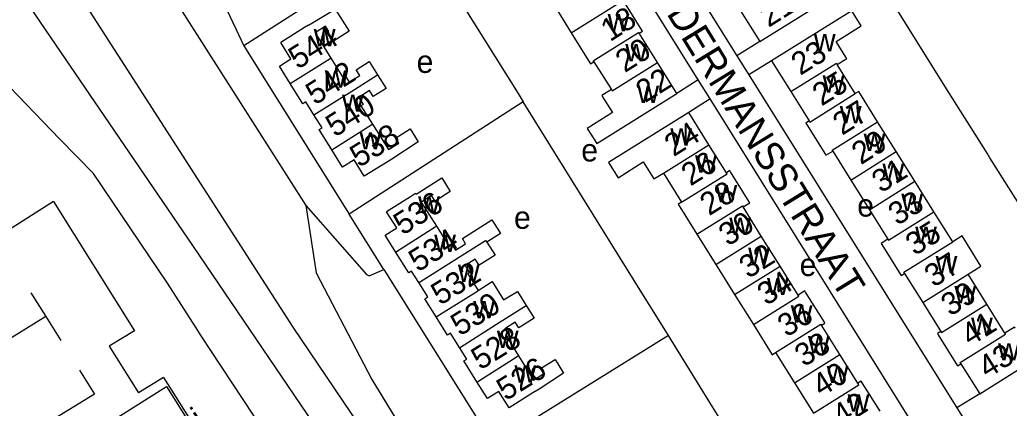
# Model space of a CAD drawing. Extents: x 159294 to 161936, y 384538 to 386517.
# Drawn here: x 159670 to 159845.8, y 385777.9 to 385846.8 of the extents above; entities that cross this region are included whole.
import ezdxf

# ---------------------------------------------------------------- set-up
doc = ezdxf.new("R2010")
doc.units = 0
for name, color, linetype in [('BLT_Basislijn', 7, 'Continuous'), ('BLT_Bebouwing', 7, 'Continuous'), ('BLT_Centroide', 7, 'Continuous'), ('BLT_Huisnummer', 7, 'Continuous'), ('BLT_Huisnummer_ tussenligend', 7, 'Continuous'), ('BLT_Huisnummer_zonder_bebouwing', 7, 'Continuous'), ('BLT_Onderverdeling_panden', 7, 'Continuous'), ('BLT_Plantopo', 7, 'Continuous'), ('BLT_Straatnaam', 7, 'Continuous'), ('BLT_Vlakafsluiter', 7, 'Continuous')]:
    doc.layers.add(name, color=color, linetype=linetype)

msp = doc.modelspace()

# ---------------------------------------------------------------- linework, layer by layer
at = {"layer": 'BLT_Basislijn'}
for p, q in [((159790.53, 385836.17), (159753.6, 385895.33)), ((159740.67, 385861.99), (159709.78, 385842.22)), ((159834.31, 385835.04), (159817.97, 385861.31)), ((159706.45, 385849.41), (159709.78, 385842.22)), ((159801.45, 385842.96), (159797.39, 385840.47)), ((159709.78, 385842.22), (159728.49, 385812.31)), ((159803.56, 385839.56), (159799.51, 385837.07)), ((159790.53, 385836.17), (159786.73, 385833.76)), ((159792.65, 385832.78), (159790.53, 385836.17)), ((159758.52, 385833.74), (159759.43, 385832.28)), ((159841.82, 385823.15), (159834.31, 385835.04)), ((159759.43, 385832.28), (159728.49, 385812.31)), ((159779.17, 385800.53), (159759.43, 385832.28)), ((159792.65, 385832.78), (159788.85, 385830.37)), ((159829.58, 385773.62), (159792.65, 385832.78)), ((159676.02, 385814.58), (159637.93, 385790.31)), ((159676.02, 385814.58), (159690.39, 385791.62)), ((159734.67, 385802.49), (159728.49, 385812.31)), ((159734.67, 385802.49), (159754.35, 385771.09)), ((159785.25, 385790.76), (159779.17, 385800.53)), ((159674.66, 385794.14), (159649.77, 385778.85)), ((159690.39, 385791.62), (159685.89, 385788.86)), ((159702.24, 385790.69), (159701.2, 385792.32)), ((159703.93, 385788.12), (159702.24, 385790.69)), ((159793.08, 385778.13), (159785.25, 385790.76)), ((159685.89, 385788.86), (159691.08, 385780.58)), ((159680.63, 385784.6), (159683.28, 385780.36)), ((159695.57, 385783.34), (159691.08, 385780.58)), ((159695.57, 385783.34), (159772.56, 385660.32)), ((159840.51, 385780.44), (159836.47, 385777.93)), ((159803.66, 385760.87), (159793.08, 385778.13))]:
    msp.add_line(p, q, dxfattribs=at)
for points in [[(159760.43, 385899.6), (159797.39, 385840.47)], [(159681.58, 385875.5), (159720.83, 385813.84)], [(159672.14, 385864.36), (159718.49, 385792.26), (159734.77, 385768.17), (159772.32, 385708.21), (159809.55, 385648.76), (159856.03, 385574.41), (159873.73, 385548.57), (159892.72, 385518.61)], [(159743.98, 385856.93), (159744.67, 385855.88), (159758.52, 385833.74)], [(159879.9, 385516.8), (159880.33, 385519.48), (159867.2, 385540.44), (159859.25, 385553.53), (159846.62, 385579.07), (159838.32, 385592.49), (159800.14, 385653.57), (159788.51, 385666.46), (159777.48, 385684.4), (159767.2, 385706.17), (159746.01, 385740.12), (159700.77, 385806.77), (159672.01, 385848.87)], [(159611.36, 385798.1), (159616.53, 385804.68), (159648.78, 385842.99), (159651.58, 385845.19), (159656.35, 385845.62), (159659.23, 385844.2), (159677.11, 385825.62)], [(159797.39, 385840.47), (159799.51, 385837.07)], [(159799.51, 385837.07), (159836.47, 385777.93)], [(159701.2, 385792.32), (159696.28, 385800.04), (159683.08, 385819.53), (159677.11, 385825.62)], [(159848.33, 385812.79), (159842.33, 385822.34), (159841.82, 385823.15)], [(159720.83, 385813.84), (159731.58, 385801.6), (159732.05, 385801.39), (159734.67, 385802.49)], [(159722.65, 385801.89), (159732.54, 385782.95), (159752.05, 385751.03), (159780.98, 385704.72), (159792.12, 385692.39), (159803.4, 385674.29), (159814.16, 385651.74), (159831.62, 385623.7)], [(159672, 385798.37), (159674.66, 385794.14)], [(159674.66, 385794.14), (159677.31, 385789.9)], [(159785.25, 385790.76), (159757.72, 385773.66), (159754.35, 385771.09)], [(159781.81, 385666), (159780.88, 385667.5), (159761.1, 385700), (159741.96, 385730.52), (159703.93, 385788.12)], [(159683.28, 385780.36), (159667.08, 385770.41), (159667.87, 385769.15)], [(159836.47, 385777.93), (159848.4, 385758.85)]]:
    msp.add_lwpolyline(points, dxfattribs=at)
at = {"layer": 'BLT_Bebouwing'}
for p, q in [((159720.6, 385845.47), (159716.36, 385842.82)), ((159721.3, 385845.9), (159720.6, 385845.47)), ((159735.45, 385821.7), (159731.21, 385819.05)), ((159736.1, 385822.1), (159735.45, 385821.7)), ((159739.42, 385815.41), (159735.17, 385812.76)), ((159762.24, 385781.27), (159761.17, 385780.6)), ((159761.17, 385780.6), (159756.93, 385777.95))]:
    msp.add_line(p, q, dxfattribs=at)
for points in [[(159801.45, 385842.96), (159815.69, 385851.85), (159813.99, 385854.54), (159809.52, 385851.73), (159807.76, 385854.53)], [(159764.61, 385849.89), (159767.96, 385844.52)], [(159780.53, 385844.99), (159777.21, 385850.3)], [(159721.3, 385845.9), (159726.03, 385848.73), (159728.5, 385844.8), (159725.71, 385843.05), (159724.71, 385844.64), (159724.92, 385844.77), (159724.34, 385845.7), (159722.46, 385844.52), (159725.27, 385840.05)], [(159798.02, 385848.45), (159801.45, 385842.96)], [(159816.74, 385840.18), (159815, 385842.96), (159819.47, 385845.77), (159817.78, 385848.46), (159803.56, 385839.56)], [(159767.96, 385844.52), (159771.29, 385839.21)], [(159780.04, 385844.44), (159780.63, 385844.81), (159780.53, 385844.99)], [(159783.28, 385839.28), (159780.04, 385844.44)], [(159718.06, 385835.53), (159716.12, 385838.63), (159718.18, 385839.92), (159716.36, 385842.82)], [(159725.27, 385840.05), (159727.35, 385836.74), (159727.75, 385836.99), (159728.52, 385835.76), (159730.42, 385836.95), (159729.78, 385837.97), (159732.1, 385839.42), (159733.57, 385837.07)], [(159771.29, 385839.21), (159771.4, 385839.03), (159771.99, 385839.4)], [(159771.99, 385839.4), (159775.1, 385834.44)], [(159786.73, 385833.76), (159783.28, 385839.28)], [(159803.56, 385839.56), (159806.99, 385834.08)], [(159815.19, 385838.88), (159816.89, 385839.95), (159816.74, 385840.18)], [(159818.42, 385833.73), (159815.19, 385838.88)], [(159722.25, 385829.97), (159720.82, 385832.25), (159720.31, 385831.93), (159718.06, 385835.53)], [(159733.57, 385837.07), (159735.09, 385834.65), (159732.79, 385833.21), (159732.13, 385834.26), (159730.22, 385833.06), (159731.02, 385831.79), (159730.62, 385831.54), (159732.65, 385828.3)], [(159773.53, 385833.18), (159775.29, 385830.36), (159770.81, 385827.55), (159772.49, 385824.86), (159786.73, 385833.76)], [(159775.1, 385834.44), (159773.4, 385833.37), (159773.53, 385833.18)], [(159806.99, 385834.08), (159810.25, 385828.88)], [(159822.38, 385828.73), (159819.02, 385834.11), (159818.42, 385833.73)], [(159788.85, 385830.37), (159774.59, 385821.48), (159776.28, 385818.78), (159780.76, 385821.59), (159782.64, 385818.57)], [(159792.42, 385824.64), (159788.85, 385830.37)], [(159725.42, 385823.77), (159723.19, 385827.34), (159723.7, 385827.65), (159722.25, 385829.97)], [(159810.25, 385828.88), (159809.65, 385828.51), (159809.77, 385828.32)], [(159825.7, 385823.43), (159822.38, 385828.73)], [(159732.65, 385828.3), (159735.49, 385823.78), (159737.32, 385824.93), (159736.75, 385825.84), (159739.34, 385827.47), (159740.8, 385825.14), (159736.1, 385822.1)], [(159809.77, 385828.32), (159813.13, 385822.94)], [(159731.21, 385819.05), (159729.4, 385821.95), (159727.36, 385820.67), (159725.42, 385823.77)], [(159795.52, 385819.68), (159792.42, 385824.64)], [(159813.13, 385822.94), (159813.21, 385822.8), (159814.4, 385823.54)], [(159814.4, 385823.54), (159817.63, 385818.38)], [(159828.99, 385818.17), (159825.7, 385823.43)], [(159782.64, 385818.57), (159782.65, 385818.57), (159784.34, 385819.63)], [(159784.34, 385819.63), (159787.57, 385814.48)], [(159796.23, 385819.85), (159796.11, 385820.05), (159795.52, 385819.68)], [(159799.56, 385814.53), (159796.23, 385819.85)], [(159740.4, 385815.88), (159744.95, 385818.76), (159746.48, 385816.34), (159743.77, 385814.63), (159743.14, 385815.62), (159741.32, 385814.47), (159744.02, 385810.21)], [(159817.63, 385818.38), (159820.92, 385813.12)], [(159832.39, 385812.75), (159828.99, 385818.17)], [(159740.4, 385815.88), (159740.33, 385815.99), (159739.42, 385815.41)], [(159787.57, 385814.48), (159786.98, 385814.1), (159790.3, 385808.78)], [(159798.49, 385813.6), (159799.67, 385814.35), (159799.56, 385814.53)], [(159736.77, 385805.64), (159734.93, 385808.59), (159736.98, 385809.87), (159735.17, 385812.76)], [(159801.72, 385808.44), (159798.49, 385813.6)], [(159820.92, 385813.12), (159824.19, 385807.87)], [(159835.72, 385807.42), (159832.39, 385812.75)], [(159744.02, 385810.21), (159746.22, 385806.72), (159746.72, 385807.03), (159747.42, 385805.93), (159749.21, 385807.06), (159748.62, 385808.01), (159753.87, 385811.33), (159755.21, 385809.21)], [(159755.21, 385809.21), (159755.42, 385808.88), (159752.97, 385807.33)], [(159752.97, 385807.33), (159754.43, 385805.03), (159751.6, 385803.24), (159750.91, 385804.34), (159749.1, 385803.2), (159749.91, 385801.91), (159749.58, 385801.7), (159751.41, 385798.76)], [(159790.3, 385808.78), (159793.65, 385803.4)], [(159805.06, 385803.09), (159801.72, 385808.44)], [(159824.19, 385807.87), (159823.01, 385807.13), (159823.12, 385806.95)], [(159838.47, 385801.69), (159840.73, 385803.11), (159837.38, 385808.46), (159835.72, 385807.43)], [(159740.89, 385800.18), (159739.62, 385802.21), (159739.12, 385801.89), (159736.77, 385805.64)], [(159823.12, 385806.95), (159826.45, 385801.63)], [(159793.65, 385803.4), (159796.99, 385798.05)], [(159808.27, 385797.94), (159805.06, 385803.09)], [(159751.41, 385798.76), (159753.92, 385800.34), (159755.95, 385797.09), (159758.39, 385798.6), (159759.95, 385796.08)], [(159826.45, 385801.63), (159826.57, 385801.44), (159827.16, 385801.81)], [(159827.16, 385801.81), (159830.39, 385796.64)], [(159841.8, 385796.33), (159838.47, 385801.69)], [(159744, 385794.08), (159741.98, 385797.31), (159742.49, 385797.63), (159740.89, 385800.18)], [(159809.58, 385798.49), (159809.46, 385798.68), (159808.27, 385797.94)], [(159796.99, 385798.05), (159800.32, 385792.71)], [(159812.92, 385793.15), (159809.58, 385798.49)], [(159759.95, 385796.08), (159761.35, 385793.83), (159758.64, 385792.14), (159758.02, 385793.12), (159756.18, 385791.98), (159756.93, 385790.77), (159756.51, 385790.51), (159758.58, 385787.16)], [(159830.39, 385796.64), (159833.61, 385791.48)], [(159845, 385791.2), (159841.8, 385796.33)], [(159748.12, 385788.62), (159746.52, 385791.17), (159746.01, 385790.85), (159744, 385794.08)], [(159800.32, 385792.71), (159803.65, 385787.37)], [(159812.43, 385792.6), (159813.03, 385792.97), (159812.92, 385793.15)], [(159815.67, 385787.43), (159812.43, 385792.6)], [(159846.82, 385792.07), (159846.7, 385792.25), (159845, 385791.2)], [(159833.61, 385791.48), (159833.02, 385791.11), (159833.14, 385790.92)], [(159833.14, 385790.92), (159836.47, 385785.59)], [(159751.22, 385782.52), (159748.89, 385786.25), (159749.4, 385786.57), (159748.12, 385788.62)], [(159840.51, 385780.44), (159854.75, 385789.33)], [(159758.58, 385787.16), (159761.26, 385782.86), (159763.1, 385784), (159762.53, 385784.92), (159765.08, 385786.51), (159766.59, 385784.08), (159762.24, 385781.27)], [(159803.65, 385787.37), (159804.24, 385787.74)], [(159804.24, 385787.74), (159807.59, 385782.39)], [(159818.89, 385782.28), (159815.67, 385787.43)], [(159836.47, 385785.59), (159836.59, 385785.4), (159837.18, 385785.77)], [(159837.18, 385785.77), (159840.51, 385780.44)], [(159756.93, 385777.95), (159755.11, 385780.85), (159753.06, 385779.57), (159751.22, 385782.52)], [(159807.59, 385782.39), (159810.98, 385776.98)], [(159819.65, 385782.38), (159819.48, 385782.65), (159818.89, 385782.28)], [(159822.82, 385777.31), (159819.65, 385782.38)]]:
    msp.add_lwpolyline(points, dxfattribs=at)
at = {"layer": 'BLT_Onderverdeling_panden'}
for points in [[(159767.96, 385844.52), (159776.02, 385849.56), (159775.89, 385849.77)], [(159771.99, 385839.4), (159771.88, 385839.58), (159779.93, 385844.61), (159780.04, 385844.44)], [(159718.06, 385835.53), (159725.17, 385839.99), (159725.27, 385840.05)], [(159775.1, 385834.44), (159775.22, 385834.24), (159783.28, 385839.28)], [(159806.99, 385834.08), (159815.05, 385839.12), (159815.19, 385838.88)], [(159722.25, 385829.97), (159729.46, 385834.49), (159733.57, 385837.07)], [(159810.25, 385828.88), (159810.36, 385828.69), (159818.42, 385833.73)], [(159814.4, 385823.54), (159814.31, 385823.68), (159822.38, 385828.73)], [(159725.42, 385823.77), (159732.52, 385828.22), (159732.65, 385828.3)], [(159784.34, 385819.63), (159792.42, 385824.64)], [(159817.63, 385818.38), (159825.7, 385823.43)], [(159787.57, 385814.48), (159795.64, 385819.49), (159795.52, 385819.68)], [(159820.92, 385813.12), (159828.99, 385818.17)], [(159790.3, 385808.78), (159798.37, 385813.79), (159798.49, 385813.6)], [(159824.19, 385807.87), (159824.31, 385807.69), (159832.39, 385812.75)], [(159736.77, 385805.64), (159736.9, 385805.72), (159743.8, 385810.07), (159744.02, 385810.21)], [(159740.89, 385800.18), (159741.02, 385800.26), (159747.91, 385804.61), (159752.76, 385807.67), (159752.97, 385807.33)], [(159793.65, 385803.4), (159801.72, 385808.44)], [(159827.16, 385801.81), (159827.05, 385802), (159835.72, 385807.42)], [(159796.99, 385798.05), (159805.06, 385803.09)], [(159830.39, 385796.64), (159838.47, 385801.69)], [(159744, 385794.08), (159744.65, 385794.49), (159751, 385798.49), (159751.41, 385798.76)], [(159800.32, 385792.71), (159808.4, 385797.75), (159808.27, 385797.94)], [(159748.12, 385788.62), (159748.29, 385788.73), (159755.36, 385793.19), (159759.95, 385796.08)], [(159833.61, 385791.48), (159833.73, 385791.29), (159841.8, 385796.33)], [(159804.24, 385787.74), (159812.32, 385792.78), (159812.43, 385792.6)], [(159837.18, 385785.77), (159837.06, 385785.96), (159845.12, 385791.01), (159845, 385791.2)], [(159751.22, 385782.52), (159751.39, 385782.63), (159758.36, 385787.02), (159758.58, 385787.16)], [(159807.59, 385782.39), (159815.67, 385787.43)], [(159810.98, 385776.98), (159819.05, 385782.01), (159818.89, 385782.28)]]:
    msp.add_lwpolyline(points, dxfattribs=at)
at = {"layer": 'BLT_Plantopo'}
msp.add_lwpolyline([(159667.23, 385763.57), (159696.1, 385781.71), (159721.25, 385741.7), (159685.44, 385719.19), (159689.02, 385713.49), (159690.98, 385714.72), (159696.4, 385706.11), (159685.96, 385699.55), (159686.3, 385699.02), (159679.89, 385694.99), (159661.02, 385725.01), (159667.48, 385729.07), (159667.7, 385728.72), (159697.07, 385747.18), (159690.56, 385757.55), (159685.67, 385754.48), (159686.88, 385752.56), (159677.77, 385746.81)], close=True, dxfattribs=at)
at = {"layer": 'BLT_Vlakafsluiter'}
msp.add_line((159720.83, 385813.84), (159722.65, 385801.89), dxfattribs=at)

# ---------------------------------------------------------------- texts
at = {"layer": 'BLT_Centroide'}
for s, p in [('w', (159774.43, 385844.81)), ('w', (159722.23, 385842.11)), ('w', (159811.06, 385841.25)), ('w', (159777.56, 385839.47)), ('e', (159740.5, 385837.41)), ('w', (159724.18, 385834.78)), ('w', (159812.62, 385833.88)), ('w', (159779.71, 385832.09)), ('w', (159727.23, 385830.5)), ('w', (159815.67, 385828.44)), ('w', (159730.37, 385823.81)), ('w', (159785.55, 385824.5)), ('w', (159819.9, 385823.56)), ('e', (159769.74, 385821.69)), ('w', (159789.95, 385819.69)), ('w', (159823.24, 385818.22)), ('w', (159793.58, 385814.44)), ('w', (159740.77, 385812.41)), ('e', (159818.76, 385811.89)), ('w', (159826.59, 385812.88)), ('e', (159757.8, 385809.72)), ('w', (159796.04, 385808.62)), ('w', (159829.05, 385807.06)), ('w', (159743.62, 385805.62)), ('w', (159799.38, 385803.28)), ('e', (159808.53, 385801.34)), ('w', (159832.68, 385801.84)), ('w', (159747.83, 385800.3)), ('w', (159802.73, 385797.94)), ('w', (159836.02, 385796.5)), ('w', (159750.55, 385793.84)), ('w', (159806.95, 385793.06)), ('w', (159838.98, 385790.88)), ('w', (159754.75, 385788.58)), ('w', (159810, 385787.62)), ('w', (159843.76, 385786.34)), ('w', (159757.88, 385782.38)), ('w', (159813.34, 385782.31)), ('w', (159817.06, 385777.25))]:
    msp.add_text(s, height=4, dxfattribs=at).set_placement(p)
at = {"layer": 'BLT_Huisnummer'}
for s, rotation, p in [('21', 32.0393, (159803.01, 385845.4)), ('18', 32.0396, (159774.84, 385842.86)), ('544', 32.121, (159719.37, 385837.94)), ('23', 32.0392, (159808.65, 385836.87)), ('22', 32.0396, (159781.06, 385832)), ('27', 32.0392, (159816.06, 385826.22)), ('24', 32.0396, (159786.15, 385822.44)), ('538', 32.1232, (159730.29, 385820.5)), ('31', 32.0392, (159822.98, 385815.98)), ('28', 32.0396, (159792.45, 385811.94)), ('536', 32.3142, (159738.03, 385808.47)), ('35', 32.0392, (159828.98, 385804.84)), ('32', 32.0396, (159799.42, 385800.79)), ('532', 31.856, (159744.68, 385796.03)), ('39', 32.0392, (159835.27, 385794.08)), ('36', 32.0396, (159806.23, 385790.38)), ('43', 32.0392, (159841.89, 385783.05)), ('526', 31.856, (159756.33, 385779.08)), ('40', 32.0396, (159812.4, 385779.77))]:
    msp.add_text(s, height=4, rotation=rotation, dxfattribs=at).set_placement(p)
at = {"layer": 'BLT_Huisnummer_ tussenligend'}
for s, rotation, p in [('20', 32.0396, (159777.46, 385837.35)), ('542', 32.1232, (159722.43, 385831.59)), ('25', 32.0392, (159812.42, 385831.42)), ('540', 32.1232, (159725.98, 385825.9)), ('29', 32.0392, (159819.4, 385821)), ('26', 32.0396, (159789.14, 385817.21)), ('33', 32.0392, (159825.89, 385810.2)), ('30', 32.0396, (159795.78, 385806.53)), ('534', 31.856, (159740.71, 385801.94)), ('37', 32.0392, (159832.33, 385799.22)), ('34', 32.0396, (159802.62, 385795.99)), ('530', 31.856, (159748.17, 385790.57)), ('41', 32.0392, (159838.82, 385788.77)), ('528', 31.856, (159751.8, 385784.54)), ('38', 32.0396, (159809.28, 385785.1)), ('42', 32.0396, (159815.93, 385774.43))]:
    msp.add_text(s, height=4, rotation=rotation, dxfattribs=at).set_placement(p)
at = {"layer": 'BLT_Huisnummer_zonder_bebouwing'}
msp.add_text('599-a t/m j', height=4, rotation=31.9529, dxfattribs=at).set_placement((159681.66, 385761.44))
at = {"layer": 'BLT_Straatnaam'}
for s, rotation, p in [('HANS VREDEMAN DE VRIESSTRAAT', 302.0626, (159843.85, 385883.43)), ('KELDERMANSSTRAAT', 301.5742, (159778.18, 385858.75))]:
    msp.add_text(s, height=5, rotation=rotation, dxfattribs=at).set_placement(p)

doc.saveas('drawing.dxf')
